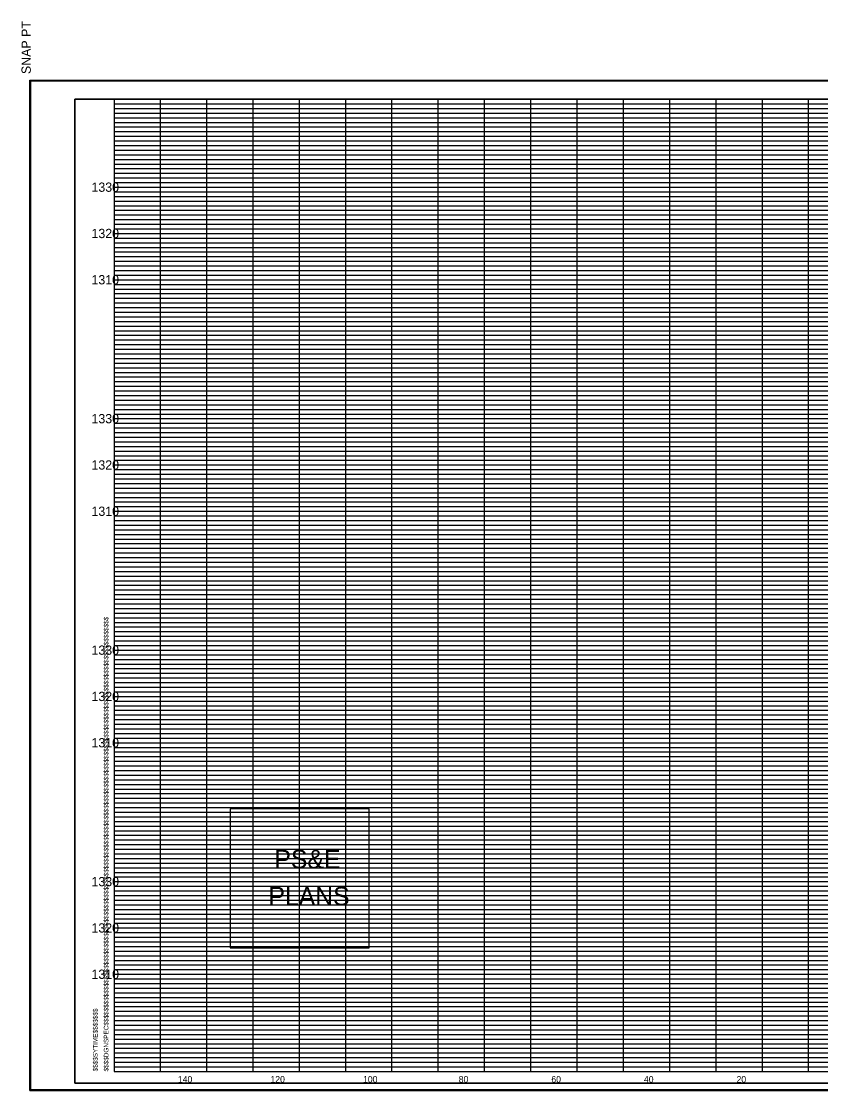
# Model space of a CAD drawing. Extents: x 980 to 1324, y 978 to 1767.
# Drawn here: x 979.9 to 1152.6, y 1265.9 to 1496.8 of the extents above; entities that cross this region are included whole.
import ezdxf

# ---------------------------------------------------------------- set-up
doc = ezdxf.new("R2010")
doc.units = 0
for name, color, linetype in [('DESIGN - SHEET - Corner Text', 7, 'Continuous'), ('DESIGN - SHEET - Light Grid', 7, 'Continuous'), ('DESIGN - SHEET - Linework', 7, 'Continuous'), ('DESIGN - SHEET - Plot Shape', 7, 'Continuous'), ('DESIGN - TYPICAL - Text', 7, 'Continuous')]:
    doc.layers.add(name, color=color, linetype=linetype)

# ---------------------------------------------------------------- blocks, each defined once
blk = doc.blocks.new('XSTSHT')
at = {"layer": 'DESIGN - SHEET - Light Grid'}
for p, q in [((0, 20.9), (8, 20.9)), ((0, 20.8), (8, 20.8)), ((8, 20.9), (16, 20.9)), ((8, 20.8), (16, 20.8)), ((0, 20.7), (8, 20.7)), ((0, 20.6), (8, 20.6)), ((8, 20.7), (16, 20.7)), ((8, 20.6), (16, 20.6)), ((0, 20.5), (8, 20.5)), ((0, 20.4), (8, 20.4)), ((8, 20.5), (16, 20.5)), ((8, 20.4), (16, 20.4)), ((0, 20.3), (8, 20.3)), ((0, 20.2), (8, 20.2)), ((0, 20.1), (8, 20.1)), ((8, 20.3), (16, 20.3)), ((8, 20.2), (16, 20.2)), ((8, 20.1), (16, 20.1)), ((0, 19.9), (8, 19.9)), ((8, 19.9), (16, 19.9)), ((0, 19.8), (8, 19.8)), ((0, 19.7), (8, 19.7)), ((8, 19.8), (16, 19.8)), ((8, 19.7), (16, 19.7)), ((0, 19.6), (8, 19.6)), ((0, 19.5), (8, 19.5)), ((0, 19.4), (8, 19.4)), ((8, 19.6), (16, 19.6)), ((8, 19.5), (16, 19.5)), ((8, 19.4), (16, 19.4)), ((0, 19.3), (8, 19.3)), ((0, 19.2), (8, 19.2)), ((8, 19.3), (16, 19.3)), ((8, 19.2), (16, 19.2)), ((0, 19.1), (8, 19.1)), ((8, 19.1), (16, 19.1)), ((0, 18.9), (8, 18.9)), ((0, 18.8), (8, 18.8)), ((8, 18.9), (16, 18.9)), ((8, 18.8), (16, 18.8)), ((0, 18.7), (8, 18.7)), ((0, 18.6), (8, 18.6)), ((0, 18.5), (8, 18.5)), ((8, 18.7), (16, 18.7)), ((8, 18.6), (16, 18.6)), ((8, 18.5), (16, 18.5)), ((0, 18.4), (8, 18.4)), ((0, 18.3), (8, 18.3)), ((8, 18.4), (16, 18.4)), ((8, 18.3), (16, 18.3)), ((0, 18.2), (8, 18.2)), ((0, 18.1), (8, 18.1)), ((8, 18.2), (16, 18.2)), ((8, 18.1), (16, 18.1)), ((0, 17.9), (8, 17.9)), ((0, 17.8), (8, 17.8)), ((8, 17.9), (16, 17.9)), ((8, 17.8), (16, 17.8)), ((0, 17.7), (8, 17.7)), ((0, 17.6), (8, 17.6)), ((8, 17.7), (16, 17.7)), ((8, 17.6), (16, 17.6)), ((0, 17.5), (8, 17.5)), ((0, 17.4), (8, 17.4)), ((8, 17.5), (16, 17.5)), ((8, 17.4), (16, 17.4)), ((0, 17.3), (8, 17.3)), ((0, 17.2), (8, 17.2)), ((0, 17.1), (8, 17.1)), ((8, 17.3), (16, 17.3)), ((8, 17.2), (16, 17.2)), ((8, 17.1), (16, 17.1)), ((0, 16.9), (8, 16.9)), ((8, 16.9), (16, 16.9)), ((0, 16.8), (8, 16.8)), ((0, 16.7), (8, 16.7)), ((8, 16.8), (16, 16.8)), ((8, 16.7), (16, 16.7)), ((0, 16.6), (8, 16.6)), ((0, 16.5), (8, 16.5)), ((0, 16.4), (8, 16.4)), ((8, 16.6), (16, 16.6)), ((8, 16.5), (16, 16.5)), ((8, 16.4), (16, 16.4)), ((0, 16.3), (8, 16.3)), ((0, 16.2), (8, 16.2)), ((8, 16.3), (16, 16.3)), ((8, 16.2), (16, 16.2)), ((0, 16.1), (8, 16.1)), ((8, 16.1), (16, 16.1)), ((0, 15.9), (8, 15.9)), ((0, 15.8), (8, 15.8)), ((8, 15.9), (16, 15.9)), ((8, 15.8), (16, 15.8)), ((0, 15.7), (8, 15.7)), ((0, 15.6), (8, 15.6)), ((0, 15.5), (8, 15.5)), ((8, 15.7), (16, 15.7)), ((8, 15.6), (16, 15.6)), ((8, 15.5), (16, 15.5)), ((0, 15.4), (8, 15.4)), ((0, 15.3), (8, 15.3)), ((8, 15.4), (16, 15.4)), ((8, 15.3), (16, 15.3)), ((0, 15.2), (8, 15.2)), ((0, 15.1), (8, 15.1)), ((8, 15.2), (16, 15.2)), ((8, 15.1), (16, 15.1)), ((0, 14.9), (8, 14.9)), ((0, 14.8), (8, 14.8)), ((8, 14.9), (16, 14.9)), ((8, 14.8), (16, 14.8)), ((0, 14.7), (8, 14.7)), ((0, 14.6), (8, 14.6)), ((8, 14.7), (16, 14.7)), ((8, 14.6), (16, 14.6)), ((0, 14.5), (8, 14.5)), ((0, 14.4), (8, 14.4)), ((8, 14.5), (16, 14.5)), ((8, 14.4), (16, 14.4)), ((0, 14.3), (8, 14.3)), ((0, 14.2), (8, 14.2)), ((0, 14.1), (8, 14.1)), ((8, 14.3), (16, 14.3)), ((8, 14.2), (16, 14.2)), ((8, 14.1), (16, 14.1)), ((0, 13.9), (8, 13.9)), ((8, 13.9), (16, 13.9)), ((0, 13.8), (8, 13.8)), ((0, 13.7), (8, 13.7)), ((8, 13.8), (16, 13.8)), ((8, 13.7), (16, 13.7)), ((0, 13.6), (8, 13.6)), ((0, 13.5), (8, 13.5)), ((0, 13.4), (8, 13.4)), ((8, 13.6), (16, 13.6)), ((8, 13.5), (16, 13.5)), ((8, 13.4), (16, 13.4)), ((0, 13.3), (8, 13.3)), ((0, 13.2), (8, 13.2)), ((8, 13.3), (16, 13.3)), ((8, 13.2), (16, 13.2)), ((0, 13.1), (8, 13.1)), ((8, 13.1), (16, 13.1)), ((0, 12.9), (8, 12.9)), ((0, 12.8), (8, 12.8)), ((8, 12.9), (16, 12.9)), ((8, 12.8), (16, 12.8)), ((0, 12.7), (8, 12.7)), ((0, 12.6), (8, 12.6)), ((0, 12.5), (8, 12.5)), ((8, 12.7), (16, 12.7)), ((8, 12.6), (16, 12.6)), ((8, 12.5), (16, 12.5)), ((0, 12.4), (8, 12.4)), ((0, 12.3), (8, 12.3)), ((8, 12.4), (16, 12.4)), ((8, 12.3), (16, 12.3)), ((0, 12.2), (8, 12.2)), ((0, 12.1), (8, 12.1)), ((8, 12.2), (16, 12.2)), ((8, 12.1), (16, 12.1)), ((0, 11.9), (8, 11.9)), ((0, 11.8), (8, 11.8)), ((8, 11.9), (16, 11.9)), ((8, 11.8), (16, 11.8)), ((0, 11.7), (8, 11.7)), ((0, 11.6), (8, 11.6)), ((8, 11.7), (16, 11.7)), ((8, 11.6), (16, 11.6)), ((0, 11.5), (8, 11.5)), ((0, 11.4), (8, 11.4)), ((8, 11.5), (16, 11.5)), ((8, 11.4), (16, 11.4)), ((0, 11.3), (8, 11.3)), ((0, 11.2), (8, 11.2)), ((0, 11.1), (8, 11.1)), ((8, 11.3), (16, 11.3)), ((8, 11.2), (16, 11.2)), ((8, 11.1), (16, 11.1)), ((0, 10.9), (8, 10.9)), ((8, 10.9), (16, 10.9)), ((0, 10.8), (8, 10.8)), ((0, 10.7), (8, 10.7)), ((8, 10.8), (16, 10.8)), ((8, 10.7), (16, 10.7)), ((0, 10.6), (8, 10.6)), ((0, 10.5), (8, 10.5)), ((0, 10.4), (8, 10.4)), ((8, 10.6), (16, 10.6)), ((8, 10.5), (16, 10.5)), ((8, 10.4), (16, 10.4)), ((0, 10.3), (8, 10.3)), ((0, 10.2), (8, 10.2)), ((8, 10.3), (16, 10.3)), ((8, 10.2), (16, 10.2)), ((0, 10.1), (8, 10.1)), ((8, 10.1), (16, 10.1)), ((0, 9.9), (8, 9.9)), ((0, 9.8), (8, 9.8)), ((0, 9.7), (8, 9.7)), ((8, 9.9), (16, 9.9)), ((8, 9.8), (16, 9.8)), ((8, 9.7), (16, 9.7)), ((0, 9.6), (8, 9.6)), ((0, 9.5), (8, 9.5)), ((8, 9.6), (16, 9.6)), ((8, 9.5), (16, 9.5)), ((0, 9.4), (8, 9.4)), ((0, 9.3), (8, 9.3)), ((8, 9.4), (16, 9.4)), ((8, 9.3), (16, 9.3)), ((0, 9.2), (8, 9.2)), ((0, 9.1), (8, 9.1)), ((8, 9.2), (16, 9.2)), ((8, 9.1), (16, 9.1)), ((0, 8.9), (8, 8.9)), ((0, 8.8), (8, 8.8)), ((8, 8.9), (16, 8.9)), ((8, 8.8), (16, 8.8)), ((0, 8.7), (8, 8.7)), ((0, 8.6), (8, 8.6)), ((8, 8.7), (16, 8.7)), ((8, 8.6), (16, 8.6)), ((0, 8.5), (8, 8.5)), ((0, 8.4), (8, 8.4)), ((8, 8.5), (16, 8.5)), ((8, 8.4), (16, 8.4)), ((0, 8.3), (8, 8.3)), ((0, 8.2), (8, 8.2)), ((0, 8.1), (8, 8.1)), ((8, 8.3), (16, 8.3)), ((8, 8.2), (16, 8.2)), ((8, 8.1), (16, 8.1)), ((0, 7.9), (8, 7.9)), ((8, 7.9), (16, 7.9)), ((0, 7.8), (8, 7.8)), ((0, 7.7), (8, 7.7)), ((8, 7.8), (16, 7.8)), ((8, 7.7), (16, 7.7)), ((0, 7.6), (8, 7.6)), ((0, 7.5), (8, 7.5)), ((0, 7.4), (8, 7.4)), ((8, 7.6), (16, 7.6)), ((8, 7.5), (16, 7.5)), ((8, 7.4), (16, 7.4)), ((0, 7.3), (8, 7.3)), ((0, 7.2), (8, 7.2)), ((8, 7.3), (16, 7.3)), ((8, 7.2), (16, 7.2)), ((0, 7.1), (8, 7.1)), ((8, 7.1), (16, 7.1)), ((0, 6.9), (8, 6.9)), ((0, 6.8), (8, 6.8)), ((0, 6.7), (8, 6.7)), ((8, 6.9), (16, 6.9)), ((8, 6.8), (16, 6.8)), ((8, 6.7), (16, 6.7)), ((0, 6.6), (8, 6.6)), ((0, 6.5), (8, 6.5)), ((8, 6.6), (16, 6.6)), ((8, 6.5), (16, 6.5)), ((0, 6.4), (8, 6.4)), ((0, 6.3), (8, 6.3)), ((8, 6.4), (16, 6.4)), ((8, 6.3), (16, 6.3)), ((0, 6.2), (8, 6.2)), ((0, 6.1), (8, 6.1)), ((8, 6.2), (16, 6.2)), ((8, 6.1), (16, 6.1)), ((0, 5.9), (8, 5.9)), ((0, 5.8), (8, 5.8)), ((8, 5.9), (16, 5.9)), ((8, 5.8), (16, 5.8)), ((0, 5.7), (8, 5.7)), ((0, 5.6), (8, 5.6)), ((8, 5.7), (16, 5.7)), ((8, 5.6), (16, 5.6)), ((0, 5.5), (8, 5.5)), ((0, 5.4), (8, 5.4)), ((8, 5.5), (16, 5.5)), ((8, 5.4), (16, 5.4)), ((0, 5.3), (8, 5.3)), ((0, 5.2), (8, 5.2)), ((0, 5.1), (8, 5.1)), ((8, 5.3), (16, 5.3)), ((8, 5.2), (16, 5.2)), ((8, 5.1), (16, 5.1)), ((0, 4.9), (8, 4.9)), ((8, 4.9), (16, 4.9)), ((0, 4.8), (8, 4.8)), ((0, 4.7), (8, 4.7)), ((8, 4.8), (16, 4.8)), ((8, 4.7), (16, 4.7)), ((0, 4.6), (8, 4.6)), ((0, 4.5), (8, 4.5)), ((0, 4.4), (8, 4.4)), ((8, 4.6), (16, 4.6)), ((8, 4.5), (16, 4.5)), ((8, 4.4), (16, 4.4)), ((0, 4.3), (8, 4.3)), ((0, 4.2), (8, 4.2)), ((8, 4.3), (16, 4.3)), ((8, 4.2), (16, 4.2)), ((0, 4.1), (8, 4.1)), ((8, 4.1), (16, 4.1)), ((0, 3.9), (8, 3.9)), ((0, 3.8), (8, 3.8)), ((0, 3.7), (8, 3.7)), ((8, 3.9), (16, 3.9)), ((8, 3.8), (16, 3.8)), ((8, 3.7), (16, 3.7)), ((0, 3.6), (8, 3.6)), ((0, 3.5), (8, 3.5)), ((8, 3.6), (16, 3.6)), ((8, 3.5), (16, 3.5)), ((0, 3.4), (8, 3.4)), ((0, 3.3), (8, 3.3)), ((8, 3.4), (16, 3.4)), ((8, 3.3), (16, 3.3)), ((0, 3.2), (8, 3.2)), ((0, 3.1), (8, 3.1)), ((8, 3.2), (16, 3.2)), ((8, 3.1), (16, 3.1)), ((0, 2.9), (8, 2.9)), ((0, 2.8), (8, 2.8)), ((8, 2.9), (16, 2.9)), ((8, 2.8), (16, 2.8)), ((0, 2.7), (8, 2.7)), ((0, 2.6), (8, 2.6)), ((8, 2.7), (16, 2.7)), ((8, 2.6), (16, 2.6)), ((0, 2.5), (8, 2.5)), ((0, 2.4), (8, 2.4)), ((8, 2.5), (16, 2.5)), ((8, 2.4), (16, 2.4)), ((0, 2.3), (8, 2.3)), ((0, 2.2), (8, 2.2)), ((0, 2.1), (8, 2.1)), ((8, 2.3), (16, 2.3)), ((8, 2.2), (16, 2.2)), ((8, 2.1), (16, 2.1)), ((0, 1.9), (8, 1.9)), ((8, 1.9), (16, 1.9)), ((0, 1.8), (8, 1.8)), ((0, 1.7), (8, 1.7)), ((8, 1.8), (16, 1.8)), ((8, 1.7), (16, 1.7)), ((0, 1.6), (8, 1.6)), ((0, 1.5), (8, 1.5)), ((0, 1.4), (8, 1.4)), ((8, 1.6), (16, 1.6)), ((8, 1.5), (16, 1.5)), ((8, 1.4), (16, 1.4)), ((0, 1.3), (8, 1.3)), ((0, 1.2), (8, 1.2)), ((8, 1.3), (16, 1.3)), ((8, 1.2), (16, 1.2)), ((0, 1.1), (8, 1.1)), ((8, 1.1), (16, 1.1)), ((0, 0.9), (8, 0.9)), ((0, 0.8), (8, 0.8)), ((0, 0.7), (8, 0.7)), ((8, 0.9), (16, 0.9)), ((8, 0.8), (16, 0.8)), ((8, 0.7), (16, 0.7)), ((0, 0.6), (8, 0.6)), ((0, 0.5), (8, 0.5)), ((8, 0.6), (16, 0.6)), ((8, 0.5), (16, 0.5)), ((0, 0.4), (8, 0.4)), ((0, 0.3), (8, 0.3)), ((8, 0.4), (16, 0.4)), ((8, 0.3), (16, 0.3)), ((0, 0.2), (8, 0.2)), ((0, 0.1), (8, 0.1)), ((8, 0.2), (16, 0.2)), ((8, 0.1), (16, 0.1))]:
    blk.add_line(p, q, dxfattribs=at)
at = {"layer": 'DESIGN - SHEET - Linework'}
for p, q in [((-1.823, -0.414), (-1.823, 21.414)), ((-1.823, 21.414), (32.217, 21.414)), ((1, 0), (1, 21)), ((2, 0), (2, 21)), ((3, 0), (3, 21)), ((4, 0), (4, 21)), ((5, 0), (5, 21)), ((6, 0), (6, 21)), ((7, 0), (7, 21)), ((8, 0), (8, 21)), ((9, 0), (9, 21)), ((10, 0), (10, 21)), ((11, 0), (11, 21)), ((12, 0), (12, 21)), ((13, 0), (13, 21)), ((14, 0), (14, 21)), ((15, 0), (15, 21)), ((0, 20), (28, 20)), ((0, 19), (32, 19)), ((0, 18), (32, 18)), ((0, 17), (32, 17)), ((0, 16), (32, 16)), ((0, 15), (32, 15)), ((0, 14), (32, 14)), ((0, 13), (32, 13)), ((0, 12), (32, 12)), ((0, 11), (32, 11)), ((0, 10), (32, 10)), ((0, 9), (32, 9)), ((0, 8), (32, 8)), ((0, 7), (32, 7)), ((0, 6), (32, 6)), ((0, 5), (32, 5)), ((0, 4), (32, 4)), ((0, 3), (32, 3)), ((0, 2), (32, 2)), ((0, 1), (32, 1)), ((-1.823, -0.414), (32.217, -0.414))]:
    blk.add_line(p, q, dxfattribs=at)
blk.add_lwpolyline([(0, 21), (0, 0), (32, 0), (32, 21), (0, 21)], dxfattribs=at)
at = {"layer": 'DESIGN - SHEET - Plot Shape'}
for points in [[(-1.803, 21.394), (32.197, 21.394), (32.197, -0.394), (-1.803, -0.394)], [(-0.85, 21), (32, 21), (32, -0.25), (-0.85, -0.25)]]:
    blk.add_lwpolyline(points, close=True, dxfattribs=at)
at = {"layer": 'DESIGN - SHEET - Corner Text'}
for s, height, p in [('  SNAP PT', 0.2, (-1.803, 21.394)), ('$$$$DGNSPEC$$$$$$$$$$$$$$$$$$$$$$$$$$$$$$$$$$$$$$$$$$$$$$$$$$$$$$$$$$$$$$$$$$$$$$$$$$$$$$$$$$$$$$$$$$$$$$$$$$$$$$$$$$$$$$$$$$$', 0.100002, (-0.126, 0)), ('$$$$SYTIME$$$$$$$', 0.1, (-0.358, 0))]:
    blk.add_text(s, height=height, rotation=90, dxfattribs=at).set_placement(p)

msp = doc.modelspace()

# ---------------------------------------------------------------- linework, layer by layer
at = {"layer": 'DESIGN - SHEET - Corner Text'}
msp.add_lwpolyline([(1025.07, 1326.7), (1025.07, 1296.7), (1055.07, 1296.7), (1055.07, 1326.7)], close=True, dxfattribs=at)
at = {"layer": 'DESIGN - SHEET - Plot Shape'}
msp.add_lwpolyline([(991.5, 1267.5), (1320, 1267.5), (1320, 1480), (991.5, 1480)], close=True, dxfattribs=at)

# ---------------------------------------------------------------- block references
at = {"layer": 'DESIGN - SHEET - Plot Shape', "xscale": 10, "yscale": 10}
msp.add_blockref('XSTSHT', (1000, 1270), dxfattribs=at)

# ---------------------------------------------------------------- texts
at = {"layer": 'DESIGN - SHEET - Corner Text'}
for s, p in [('PS&E', (1034.59, 1313.87)), ('PLANS', (1033.31, 1305.87))]:
    msp.add_text(s, height=4, dxfattribs=at).set_placement(p)
at = {"layer": 'DESIGN - TYPICAL - Text'}
for s, height, p in [('     1330     ', 2, (991.37, 1460)), ('     1320     ', 2, (991.37, 1450)), ('     1310     ', 2, (991.37, 1440)), ('     1330     ', 2, (991.37, 1410)), ('     1320     ', 2, (991.37, 1400)), ('     1310     ', 2, (991.37, 1390)), ('     1330     ', 2, (991.37, 1360)), ('     1320     ', 2, (991.37, 1350)), ('     1310     ', 2, (991.37, 1340)), ('     1330     ', 2, (991.37, 1310)), ('     1320     ', 2, (991.37, 1300)), ('     1310     ', 2, (991.37, 1290)), ('     140     ', 1.4, (1011.14, 1267.6)), ('     120     ', 1.4, (1031.14, 1267.6)), ('     100     ', 1.4, (1051.14, 1267.6)), ('     80     ', 1.4, (1071.82, 1267.6)), ('     60     ', 1.4, (1091.82, 1267.6)), ('     40     ', 1.4, (1111.82, 1267.6)), ('     20     ', 1.4, (1131.82, 1267.6))]:
    msp.add_text(s, height=height, dxfattribs=at).set_placement(p)

doc.saveas('drawing.dxf')
